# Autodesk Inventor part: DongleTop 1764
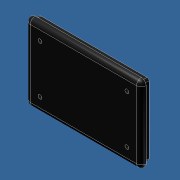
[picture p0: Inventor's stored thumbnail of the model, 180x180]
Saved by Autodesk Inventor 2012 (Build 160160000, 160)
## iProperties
Created: 2010-01
Part Number: DongleTop 1764
Document SubType Name: Modeling
Designer: jgehrig
Density: 1 g/cm^3
Material: Default
Author: jgehrig
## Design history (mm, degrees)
sketch "Sketch1"
  geometry: L1 (-34.141, 54.042)-(42.059, 54.042); L2 (42.059, 54.042)-(42.059, 3.242); L3 (42.059, 3.242)-(-34.141, 3.242); L4 (-34.141, 3.242)-(-34.141, 54.042); 1 further point
  constraints: 8 end point, 2 parallel, 1 horizontal, 1 perpendicular
  dimensions: "d0" = 50.8 distance of L3.end L1.start; "d1" = 76.2 distance of L2.end L3.end
extrude "Extrusion1" new body sketch "Sketch1" distance "d2" = 6.985; taper "d3" = 0 deg
fillet "Fillet1" dims "d4" = 3.175
shell "Shell1" dims "d5" = 4.445
sketch "Sketch2"
  geometry: L1 (-38.884, 3.242)-(30.966, 3.242) reference; L2 (34.141, 6.417)-(34.141, 50.867) reference; L3 (30.966, 54.042)-(-38.884, 54.042) reference; L4 (-42.059, 50.867)-(-42.059, 6.417) reference; L5 (30.966, 5.147)-(-38.884, 5.147); L6 (-40.154, 6.417)-(-40.154, 50.867); L7 (-38.884, 52.137)-(30.966, 52.137); L8 (32.236, 50.867)-(32.236, 6.417); A1 r 3.175 centre (-38.884, 6.417) between (-42.059, 6.417) and (-38.884, 3.242) reference; A2 r 3.175 centre (30.966, 6.417) between (30.966, 3.242) and (34.141, 6.417) reference; A3 r 3.175 centre (30.966, 50.867) between (34.141, 50.867) and (30.966, 54.042) reference; A4 r 3.175 centre (-38.884, 50.867) between (-38.884, 54.042) and (-42.059, 50.867) reference; A5 r 1.27 centre (30.966, 6.417) between (30.966, 5.147) and (32.236, 6.417); A6 r 1.27 centre (-38.884, 6.417) between (-40.154, 6.417) and (-38.884, 5.147); A7 r 1.27 centre (-38.884, 50.867) between (-38.884, 52.137) and (-40.154, 50.867); A8 r 1.27 centre (30.966, 50.867) between (32.236, 50.867) and (30.966, 52.137); 1 further point
  constraints: 8 end point, 8 point on circle, 4 centre point, 7 other
  dimensions: "d6" = 1.905 distance between parallel lines of L1 L5
fillet "Fillet2" dims "d7" = 3.175
extrude "Extrusion2" cut sketch "Sketch2" distance "d8" = 3.81; taper "d9" = 0 deg
sketch "Sketch3"
  geometry: L1 (0, 0)-(60.96, 0) reference; L2 (-3.175, -38.735)-(-3.175, -3.175) reference; L3 (65.405, 2.54)-(-4.445, 2.54) reference; L4 (-5.715, 1.27)-(-5.715, -43.18) reference; L5 (-7.62, -43.18)-(-7.62, 1.27) reference; L6 (-4.445, 4.445)-(65.405, 4.445) reference; C1 r 3.175 at (1.905, -5.08); C2 r 3.175 at (59.055, -5.08); C3 r 3.175 at (1.905, -36.83); C4 r 3.175 at (59.055, -36.83); 1 further point
  constraints: 4 centre point, 1 horizontal, 1 vertical, 6 other
  dimensions: "d10" = 6.35 diameter of C1; "d15" = 57.15 distance of C1.centre C2.centre; "d18" = 31.75 distance of C1.centre C3.centre; "d32" = 9.525 distance from line of L5 C1.centre; "d33" = 9.525 distance from line of L6 C1.centre
extrude "Extrusion3" join sketch "Sketch3" distance "d21" = 4.445; taper "d22" = 0 deg
sketch "Sketch4"
  geometry: L1 (-1.905, 5.08)-(59.055, 5.08) reference; L2 (-5.08, -33.655)-(-5.08, 1.905) reference; L3 (59.055, -36.83)-(-1.905, -36.83) reference; L4 (62.23, 1.905)-(62.23, -33.655) reference; C1 r 3.175 at (57.15, -31.75) reference; C2 r 3.175 at (0, -31.75) reference; C3 r 3.175 at (57.15, 0) reference; C4 r 3.175 at (0, 0) reference; C5 r 1.27 at (0, 0); C6 r 1.27 at (0, -31.75); C7 r 1.27 at (57.15, -31.75); C8 r 1.27 at (57.15, 0); A1 r 3.175 centre (59.055, 1.905) between (62.23, 1.905) and (59.055, 5.08) reference; A2 r 3.175 centre (-1.905, 1.905) between (-1.905, 5.08) and (-5.08, 1.905) reference; A3 r 3.175 centre (-1.905, -33.655) between (-5.08, -33.655) and (-1.905, -36.83) reference; A4 r 3.175 centre (59.055, -33.655) between (59.055, -36.83) and (62.23, -33.655) reference; 1 further point
  constraints: 4 centre point, 4 coincident
  dimensions: "d23" = 2.54 diameter of C5; "d24" = 2.54 diameter of C8; "d25" = 2.54 diameter of C7; "d26" = 2.54 diameter of C6
extrude "Extrusion4" cut sketch "Sketch4" stored distance "d27" = 6.985; taper "d28" = 0 deg
body "Solid1"
node "Projected Loop1"
